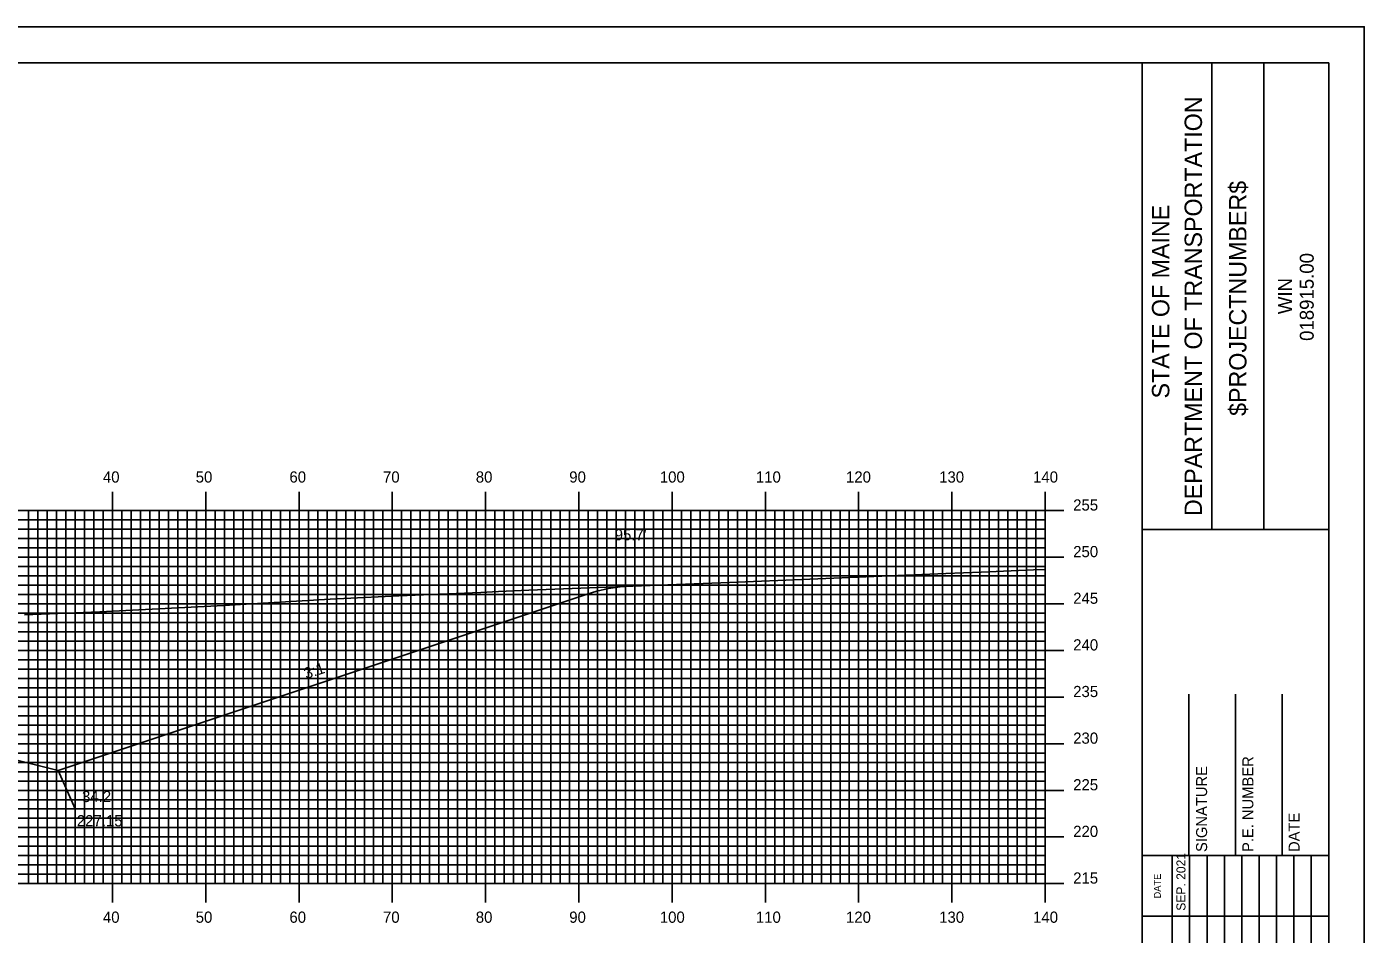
# Model space of a CAD drawing. Extents: x 1818063 to 1818407, y 442591 to 442811.
# Drawn here: x 1818259.9 to 1818403.3, y 442713.2 to 442810.5 of the extents above; entities that cross this region are included whole.
import ezdxf

# ---------------------------------------------------------------- set-up
doc = ezdxf.new("R2010")
doc.units = 0
for name, color, linetype in [('ANNOTATION', 7, 'Continuous'), ('BORDER', 7, 'Continuous'), ('D_Roadway_Centerline', 7, 'Continuous'), ('D_Roadway_SlopeLines', 7, 'Continuous'), ('D_Text_Standard', 7, 'Continuous'), ('H_V ANNOTATION', 7, 'Continuous'), ('MAJOR', 7, 'Continuous'), ('MINOR', 7, 'Continuous'), ('PLOT BOUNDARY', 7, 'Continuous'), ('S_Roadway_Centerline', 7, 'Continuous')]:
    doc.layers.add(name, color=color, linetype=linetype)

msp = doc.modelspace()

# ---------------------------------------------------------------- linework, layer by layer
at = {"layer": 'ANNOTATION'}
msp.add_lwpolyline([(1818270.81, 442726.68), (1818265.12, 442726.68), (1818263.3, 442730.81)], dxfattribs=at)
at = {"layer": 'BORDER'}
for p, q in [((1818379.53, 442596.67), (1818379.53, 442806.67)), ((1818386.98, 442756.66), (1818386.98, 442806.66)), ((1818392.57, 442756.66), (1818392.57, 442806.66)), ((1818379.53, 442756.65), (1818399.53, 442756.65)), ((1818384.53, 442721.67), (1818384.53, 442738.97)), ((1818389.53, 442721.67), (1818389.53, 442738.97)), ((1818394.53, 442721.67), (1818394.53, 442738.97)), ((1818379.53, 442721.67), (1818399.53, 442721.67))]:
    msp.add_line(p, q, dxfattribs=at)
msp.add_lwpolyline([(1818079.53, 442596.67), (1818399.53, 442596.67), (1818399.53, 442806.67), (1818079.53, 442806.67)], close=True, dxfattribs=at)
for points in [[(1818382.76, 442715.17), (1818382.76, 442721.67)], [(1818384.62, 442686.68), (1818384.62, 442721.67)], [(1818386.48, 442721.67), (1818386.48, 442686.68)], [(1818388.35, 442686.68), (1818388.35, 442721.67)], [(1818390.21, 442686.68), (1818390.21, 442721.67)], [(1818392.07, 442686.68), (1818392.07, 442721.67)], [(1818393.94, 442686.68), (1818393.94, 442721.67)], [(1818395.8, 442686.68), (1818395.8, 442721.67)], [(1818397.66, 442686.68), (1818397.66, 442721.67)], [(1818382.76, 442686.68), (1818382.76, 442720.26)], [(1818379.53, 442715.17), (1818399.53, 442715.17)]]:
    msp.add_lwpolyline(points, dxfattribs=at)
at = {"layer": 'D_Roadway_Centerline'}
msp.add_lwpolyline([(1818170.17, 442737.93), (1818171.42, 442738.01), (1818172.67, 442737.95), (1818173.92, 442737.75), (1818175.17, 442737.4), (1818194.95, 442730.81), (1818198.95, 442731.81), (1818209.13, 442734.35), (1818217.13, 442734.67), (1818229.13, 442734.91), (1818241.13, 442734.67), (1818249.13, 442734.35), (1818259.3, 442731.81), (1818263.3, 442730.81), (1818319.81, 442749.65), (1818321.06, 442750.02), (1818322.31, 442750.3), (1818323.56, 442750.48), (1818324.81, 442750.58)], dxfattribs=at)
at = {"layer": 'D_Roadway_SlopeLines'}
for points in [[(1818263.3, 442730.81), (1818319.81, 442749.65), (1818321.06, 442750.02), (1818322.31, 442750.3), (1818323.56, 442750.48), (1818324.81, 442750.58)], [(1818249.13, 442734.35), (1818263.3, 442730.81)]]:
    msp.add_lwpolyline(points, dxfattribs=at)
at = {"layer": 'MAJOR'}
for p, q in [((1818269.13, 442760.67), (1818269.13, 442758.67)), ((1818279.13, 442760.67), (1818279.13, 442758.67)), ((1818289.13, 442760.67), (1818289.13, 442758.67)), ((1818299.13, 442760.67), (1818299.13, 442758.67)), ((1818309.13, 442760.67), (1818309.13, 442758.67)), ((1818319.13, 442760.67), (1818319.13, 442758.67)), ((1818329.13, 442760.67), (1818329.13, 442758.67)), ((1818339.13, 442760.67), (1818339.13, 442758.67)), ((1818349.13, 442760.67), (1818349.13, 442758.67)), ((1818359.13, 442760.67), (1818359.13, 442758.67)), ((1818369.13, 442760.67), (1818369.13, 442758.67)), ((1818089.13, 442758.67), (1818369.13, 442758.67)), ((1818089.13, 442758.67), (1818369.13, 442758.67)), ((1818269.13, 442718.67), (1818269.13, 442758.67)), ((1818279.13, 442718.67), (1818279.13, 442758.67)), ((1818289.13, 442718.67), (1818289.13, 442758.67)), ((1818299.13, 442718.67), (1818299.13, 442758.67)), ((1818309.13, 442718.67), (1818309.13, 442758.67)), ((1818319.13, 442718.67), (1818319.13, 442758.67)), ((1818329.13, 442718.67), (1818329.13, 442758.67)), ((1818339.13, 442718.67), (1818339.13, 442758.67)), ((1818349.13, 442718.67), (1818349.13, 442758.67)), ((1818359.13, 442718.67), (1818359.13, 442758.67)), ((1818371.13, 442758.67), (1818367.12, 442758.67)), ((1818369.13, 442718.67), (1818369.13, 442758.67)), ((1818369.13, 442718.67), (1818369.13, 442758.67)), ((1818089.13, 442753.67), (1818369.13, 442753.67)), ((1818371.13, 442753.67), (1818367.12, 442753.67)), ((1818089.13, 442748.67), (1818369.13, 442748.67)), ((1818371.13, 442748.67), (1818367.12, 442748.67)), ((1818089.13, 442743.67), (1818369.13, 442743.67)), ((1818371.13, 442743.67), (1818367.12, 442743.67)), ((1818089.13, 442738.67), (1818369.13, 442738.67)), ((1818371.13, 442738.67), (1818367.12, 442738.67)), ((1818089.13, 442733.67), (1818369.13, 442733.67)), ((1818371.13, 442733.67), (1818367.12, 442733.67)), ((1818089.13, 442728.67), (1818369.13, 442728.67)), ((1818371.13, 442728.67), (1818367.12, 442728.67)), ((1818089.13, 442723.67), (1818369.13, 442723.67)), ((1818371.13, 442723.67), (1818367.12, 442723.67)), ((1818089.13, 442718.67), (1818369.13, 442718.67)), ((1818089.13, 442718.67), (1818369.13, 442718.67)), ((1818269.13, 442716.66), (1818269.13, 442718.67)), ((1818279.13, 442716.66), (1818279.13, 442718.67)), ((1818289.13, 442716.66), (1818289.13, 442718.67)), ((1818299.13, 442716.66), (1818299.13, 442718.67)), ((1818309.13, 442716.66), (1818309.13, 442718.67)), ((1818319.13, 442716.66), (1818319.13, 442718.67)), ((1818329.13, 442716.66), (1818329.13, 442718.67)), ((1818339.13, 442716.66), (1818339.13, 442718.67)), ((1818349.13, 442716.66), (1818349.13, 442718.67)), ((1818359.13, 442716.66), (1818359.13, 442718.67)), ((1818371.13, 442718.67), (1818367.12, 442718.67)), ((1818369.13, 442716.66), (1818369.13, 442718.67))]:
    msp.add_line(p, q, dxfattribs=at)
at = {"layer": 'MINOR'}
for p, q in [((1818260.13, 442718.67), (1818260.13, 442758.67)), ((1818261.13, 442718.67), (1818261.13, 442758.67)), ((1818262.13, 442718.67), (1818262.13, 442758.67)), ((1818263.13, 442718.67), (1818263.13, 442758.67)), ((1818264.13, 442718.67), (1818264.13, 442758.67)), ((1818265.13, 442718.67), (1818265.13, 442758.67)), ((1818266.13, 442718.67), (1818266.13, 442758.67)), ((1818267.13, 442718.67), (1818267.13, 442758.67)), ((1818268.13, 442718.67), (1818268.13, 442758.67)), ((1818270.13, 442718.67), (1818270.13, 442758.67)), ((1818271.13, 442718.67), (1818271.13, 442758.67)), ((1818272.13, 442718.67), (1818272.13, 442758.67)), ((1818273.13, 442718.67), (1818273.13, 442758.67)), ((1818274.13, 442718.67), (1818274.13, 442758.67)), ((1818275.13, 442718.67), (1818275.13, 442758.67)), ((1818276.13, 442718.67), (1818276.13, 442758.67)), ((1818277.13, 442718.67), (1818277.13, 442758.67)), ((1818278.13, 442718.67), (1818278.13, 442758.67)), ((1818280.13, 442718.67), (1818280.13, 442758.67)), ((1818281.13, 442718.67), (1818281.13, 442758.67)), ((1818282.13, 442718.67), (1818282.13, 442758.67)), ((1818283.13, 442718.67), (1818283.13, 442758.67)), ((1818284.13, 442718.67), (1818284.13, 442758.67)), ((1818285.13, 442718.67), (1818285.13, 442758.67)), ((1818286.13, 442718.67), (1818286.13, 442758.67)), ((1818287.13, 442718.67), (1818287.13, 442758.67)), ((1818288.13, 442718.67), (1818288.13, 442758.67)), ((1818290.13, 442718.67), (1818290.13, 442758.67)), ((1818291.13, 442718.67), (1818291.13, 442758.67)), ((1818292.13, 442718.67), (1818292.13, 442758.67)), ((1818293.13, 442718.67), (1818293.13, 442758.67)), ((1818294.13, 442718.67), (1818294.13, 442758.67)), ((1818295.13, 442718.67), (1818295.13, 442758.67)), ((1818296.13, 442718.67), (1818296.13, 442758.67)), ((1818297.13, 442718.67), (1818297.13, 442758.67)), ((1818298.13, 442718.67), (1818298.13, 442758.67)), ((1818300.13, 442718.67), (1818300.13, 442758.67)), ((1818301.13, 442718.67), (1818301.13, 442758.67)), ((1818302.13, 442718.67), (1818302.13, 442758.67)), ((1818303.13, 442718.67), (1818303.13, 442758.67)), ((1818304.13, 442718.67), (1818304.13, 442758.67)), ((1818305.13, 442718.67), (1818305.13, 442758.67)), ((1818306.13, 442718.67), (1818306.13, 442758.67)), ((1818307.13, 442718.67), (1818307.13, 442758.67)), ((1818308.13, 442718.67), (1818308.13, 442758.67)), ((1818310.13, 442718.67), (1818310.13, 442758.67)), ((1818311.13, 442718.67), (1818311.13, 442758.67)), ((1818312.13, 442718.67), (1818312.13, 442758.67)), ((1818313.13, 442718.67), (1818313.13, 442758.67)), ((1818314.13, 442718.67), (1818314.13, 442758.67)), ((1818315.13, 442718.67), (1818315.13, 442758.67)), ((1818316.13, 442718.67), (1818316.13, 442758.67)), ((1818317.13, 442718.67), (1818317.13, 442758.67)), ((1818318.13, 442718.67), (1818318.13, 442758.67)), ((1818320.13, 442718.67), (1818320.13, 442758.67)), ((1818321.13, 442718.67), (1818321.13, 442758.67)), ((1818322.13, 442718.67), (1818322.13, 442758.67)), ((1818323.13, 442718.67), (1818323.13, 442758.67)), ((1818324.13, 442718.67), (1818324.13, 442758.67)), ((1818325.13, 442718.67), (1818325.13, 442758.67)), ((1818326.13, 442718.67), (1818326.13, 442758.67)), ((1818327.13, 442718.67), (1818327.13, 442758.67)), ((1818328.13, 442718.67), (1818328.13, 442758.67)), ((1818330.13, 442718.67), (1818330.13, 442758.67)), ((1818331.13, 442718.67), (1818331.13, 442758.67)), ((1818332.13, 442718.67), (1818332.13, 442758.67)), ((1818333.13, 442718.67), (1818333.13, 442758.67)), ((1818334.13, 442718.67), (1818334.13, 442758.67)), ((1818335.13, 442718.67), (1818335.13, 442758.67)), ((1818336.13, 442718.67), (1818336.13, 442758.67)), ((1818337.13, 442718.67), (1818337.13, 442758.67)), ((1818338.13, 442718.67), (1818338.13, 442758.67)), ((1818340.13, 442718.67), (1818340.13, 442758.67)), ((1818341.13, 442718.67), (1818341.13, 442758.67)), ((1818342.13, 442718.67), (1818342.13, 442758.67)), ((1818343.13, 442718.67), (1818343.13, 442758.67)), ((1818344.13, 442718.67), (1818344.13, 442758.67)), ((1818345.13, 442718.67), (1818345.13, 442758.67)), ((1818346.13, 442718.67), (1818346.13, 442758.67)), ((1818347.13, 442718.67), (1818347.13, 442758.67)), ((1818348.13, 442718.67), (1818348.13, 442758.67)), ((1818350.13, 442718.67), (1818350.13, 442758.67)), ((1818351.13, 442718.67), (1818351.13, 442758.67)), ((1818352.13, 442718.67), (1818352.13, 442758.67)), ((1818353.13, 442718.67), (1818353.13, 442758.67)), ((1818354.13, 442718.67), (1818354.13, 442758.67)), ((1818355.13, 442718.67), (1818355.13, 442758.67)), ((1818356.13, 442718.67), (1818356.13, 442758.67)), ((1818357.13, 442718.67), (1818357.13, 442758.67)), ((1818358.13, 442718.67), (1818358.13, 442758.67)), ((1818360.13, 442718.67), (1818360.13, 442758.67)), ((1818361.13, 442718.67), (1818361.13, 442758.67)), ((1818362.13, 442718.67), (1818362.13, 442758.67)), ((1818363.13, 442718.67), (1818363.13, 442758.67)), ((1818364.13, 442718.67), (1818364.13, 442758.67)), ((1818365.13, 442718.67), (1818365.13, 442758.67)), ((1818366.13, 442718.67), (1818366.13, 442758.67)), ((1818367.13, 442718.67), (1818367.13, 442758.67)), ((1818368.13, 442718.67), (1818368.13, 442758.67)), ((1818089.13, 442757.67), (1818369.13, 442757.67)), ((1818369.13, 442757.67), (1818367.12, 442757.67)), ((1818089.13, 442756.67), (1818369.13, 442756.67)), ((1818089.13, 442755.67), (1818369.13, 442755.67)), ((1818369.13, 442756.67), (1818367.12, 442756.67)), ((1818369.13, 442755.67), (1818367.12, 442755.67)), ((1818089.13, 442754.67), (1818369.13, 442754.67)), ((1818369.13, 442754.67), (1818367.12, 442754.67)), ((1818089.13, 442752.67), (1818369.13, 442752.67)), ((1818369.13, 442752.67), (1818367.12, 442752.67)), ((1818089.13, 442751.67), (1818369.13, 442751.67)), ((1818369.13, 442751.67), (1818367.12, 442751.67)), ((1818089.13, 442750.67), (1818369.13, 442750.67)), ((1818369.13, 442750.67), (1818367.12, 442750.67)), ((1818089.13, 442749.67), (1818369.13, 442749.67)), ((1818369.13, 442749.67), (1818367.12, 442749.67)), ((1818089.13, 442747.67), (1818369.13, 442747.67)), ((1818369.13, 442747.67), (1818367.12, 442747.67)), ((1818089.13, 442746.67), (1818369.13, 442746.67)), ((1818089.13, 442745.67), (1818369.13, 442745.67)), ((1818369.13, 442746.67), (1818367.12, 442746.67)), ((1818369.13, 442745.67), (1818367.12, 442745.67)), ((1818089.13, 442744.67), (1818369.13, 442744.67)), ((1818369.13, 442744.67), (1818367.12, 442744.67)), ((1818089.13, 442742.67), (1818369.13, 442742.67)), ((1818369.13, 442742.67), (1818367.12, 442742.67)), ((1818089.13, 442741.67), (1818369.13, 442741.67)), ((1818369.13, 442741.67), (1818367.12, 442741.67)), ((1818089.13, 442740.67), (1818369.13, 442740.67)), ((1818369.13, 442740.67), (1818367.12, 442740.67)), ((1818089.13, 442739.67), (1818369.13, 442739.67)), ((1818369.13, 442739.67), (1818367.12, 442739.67)), ((1818089.13, 442737.67), (1818369.13, 442737.67)), ((1818369.13, 442737.67), (1818367.12, 442737.67)), ((1818089.13, 442736.67), (1818369.13, 442736.67)), ((1818089.13, 442735.67), (1818369.13, 442735.67)), ((1818369.13, 442736.67), (1818367.12, 442736.67)), ((1818369.13, 442735.67), (1818367.12, 442735.67)), ((1818089.13, 442734.67), (1818369.13, 442734.67)), ((1818369.13, 442734.67), (1818367.12, 442734.67)), ((1818089.13, 442732.67), (1818369.13, 442732.67)), ((1818369.13, 442732.67), (1818367.12, 442732.67)), ((1818089.13, 442731.67), (1818369.13, 442731.67)), ((1818369.13, 442731.67), (1818367.12, 442731.67)), ((1818089.13, 442730.67), (1818369.13, 442730.67)), ((1818369.13, 442730.67), (1818367.12, 442730.67)), ((1818089.13, 442729.67), (1818369.13, 442729.67)), ((1818369.13, 442729.67), (1818367.12, 442729.67)), ((1818089.13, 442727.67), (1818369.13, 442727.67)), ((1818369.13, 442727.67), (1818367.12, 442727.67)), ((1818089.13, 442726.67), (1818369.13, 442726.67)), ((1818089.13, 442725.67), (1818369.13, 442725.67)), ((1818369.13, 442726.67), (1818367.12, 442726.67)), ((1818369.13, 442725.67), (1818367.12, 442725.67)), ((1818089.13, 442724.67), (1818369.13, 442724.67)), ((1818369.13, 442724.67), (1818367.12, 442724.67)), ((1818089.13, 442722.67), (1818369.13, 442722.67)), ((1818369.13, 442722.67), (1818367.12, 442722.67)), ((1818089.13, 442721.67), (1818369.13, 442721.67)), ((1818369.13, 442721.67), (1818367.12, 442721.67)), ((1818089.13, 442720.67), (1818369.13, 442720.67)), ((1818089.13, 442719.67), (1818369.13, 442719.67)), ((1818369.13, 442720.67), (1818367.12, 442720.67)), ((1818369.13, 442719.67), (1818367.12, 442719.67))]:
    msp.add_line(p, q, dxfattribs=at)
at = {"layer": 'PLOT BOUNDARY'}
msp.add_lwpolyline([(1818063.34, 442590.55), (1818403.34, 442590.55), (1818403.34, 442810.55), (1818063.34, 442810.55)], close=True, dxfattribs=at)
at = {"layer": 'S_Roadway_Centerline'}
msp.add_lwpolyline([(1818259.69, 442747.49), (1818267.78, 442747.82), (1818281.06, 442748.48), (1818292.47, 442749.17), (1818293.94, 442749.25), (1818299.84, 442749.54), (1818308.63, 442749.88), (1818310.53, 442749.99), (1818313.78, 442750.15), (1818326.79, 442750.65), (1818335.28, 442750.94), (1818343.9, 442751.33), (1818358.47, 442751.93), (1818362.26, 442752.08), (1818367.86, 442752.3), (1818369.13, 442752.35)], dxfattribs=at)

# ---------------------------------------------------------------- texts
at = {"layer": 'ANNOTATION'}
msp.add_text('3:1', height=1.2, rotation=18.4348, dxfattribs=at).set_placement((1818289.89, 442740.58))
for s, p in [("34.2'", (1818265.86, 442727.41)), ('227.15', (1818265.3, 442724.81))]:
    msp.add_text(s, height=1.2, dxfattribs=at).set_placement(p)
at = {"layer": 'BORDER'}
for s, height, p in [('DEPARTMENT OF TRANSPORTATION', 1.8635, (1818385.94, 442758.08)), ('$PROJECTNUMBER$', 1.8635, (1818390.71, 442768.82)), ('STATE OF MAINE', 1.8635, (1818382.44, 442770.69)), ('018915.00', 1.491, (1818397.92, 442776.86)), ('WIN', 1.491, (1818395.6, 442779.73)), ('SIGNATURE', 1.181, (1818386.49, 442722.06)), ('P.E. NUMBER', 1.1811, (1818391.45, 442722.06)), ('DATE', 1.181, (1818396.41, 442722.06)), ('SEP. 2021', 0.969, (1818384.17, 442715.76)), ('DATE', 0.743, (1818381.53, 442717.08))]:
    msp.add_text(s, height=height, rotation=90, dxfattribs=at).set_placement(p)
at = {"layer": 'D_Text_Standard'}
msp.add_text("95.7'", height=1.2, dxfattribs=at).set_placement((1818322.97, 442755.48))
at = {"layer": 'H_V ANNOTATION'}
for s, p in [('40', (1818268.1, 442761.67)), ('50', (1818278.05, 442761.67)), ('60', (1818288.1, 442761.67)), ('70', (1818298.13, 442761.67)), ('80', (1818308.08, 442761.67)), ('90', (1818318.1, 442761.67)), ('100', (1818327.81, 442761.67)), ('110', (1818338.11, 442761.67)), ('120', (1818347.77, 442761.67)), ('130', (1818357.76, 442761.67)), ('140', (1818367.83, 442761.67)), ('255', (1818372.13, 442758.67)), ('250', (1818372.13, 442753.67)), ('245', (1818372.13, 442748.67)), ('240', (1818372.13, 442743.67)), ('235', (1818372.13, 442738.67)), ('230', (1818372.13, 442733.67)), ('225', (1818372.13, 442728.67)), ('220', (1818372.13, 442723.67)), ('215', (1818372.13, 442718.67)), ('40', (1818268.1, 442714.47)), ('50', (1818278.05, 442714.47)), ('60', (1818288.1, 442714.47)), ('70', (1818298.13, 442714.47)), ('80', (1818308.08, 442714.47)), ('90', (1818318.1, 442714.47)), ('100', (1818327.81, 442714.47)), ('110', (1818338.11, 442714.47)), ('120', (1818347.77, 442714.47)), ('130', (1818357.76, 442714.47)), ('140', (1818367.83, 442714.47))]:
    msp.add_text(s, height=1.2, dxfattribs=at).set_placement(p)

doc.saveas('drawing.dxf')
